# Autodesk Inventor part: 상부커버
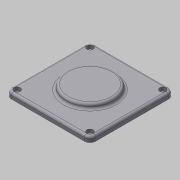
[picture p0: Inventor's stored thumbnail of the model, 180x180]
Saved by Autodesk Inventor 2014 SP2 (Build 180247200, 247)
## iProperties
Created: 2018-09
Part Number: 상부커버
Document SubType Name: Modeling
Density: 2.71 g/cm^3
Material: 알루미늄 6061
Mass: 249.405 g
Surface Area: 254.001 cm^2
Volume: 92.0315 cm^3
Appearance: 알루미늄 - 평지
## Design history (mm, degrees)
sketch "스케치5"
  geometry: L1 (-52.5, -52.5)-(52.5, -52.5); L2 (52.5, -52.5)-(52.5, 52.5); L3 (52.5, 52.5)-(-52.5, 52.5); L4 (-52.5, 52.5)-(-52.5, -52.5); L5 (-52.5, -52.5)-(52.5, 52.5); L6 (52.5, -52.5)-(-52.5, 52.5); 1 further point
  constraints: 12 end point, 2 midpoint, 2 parallel, 1 horizontal, 1 perpendicular
  dimensions: "d35" = 105 distance of L3.end L2.end; "d36" = 105 distance of L2.end L1.end
extrude "돌출4" new body sketch "스케치5" distance "d37" = 7; taper "d38" = 0 deg
fillet "모깎기4" dims "d39" = 7
sketch "스케치2"
  geometry: C1 r 30 at (0, 0); 2 further points
  constraints: 2 coincident, 1 centre point
  dimensions: "d4" = 60 diameter of C1
extrude "돌출3" join sketch "스케치2" distance "d5" = 6; taper "d6" = 0 deg
fillet "모깎기1" dims "d7" = 3
sketch "스케치4"
  geometry: L1 (52.5, -45.5)-(52.5, 45.5) reference; L2 (-45.5, -52.5)-(45.5, -52.5) reference; L3 (-52.5, 45.5)-(-52.5, -45.5) reference; L4 (45.5, 52.5)-(-45.5, 52.5) reference; A1 r 7 centre (45.5, 45.5) between (52.5, 45.5) and (45.5, 52.5) reference; A2 r 7 centre (45.5, -45.5) between (45.5, -52.5) and (52.5, -45.5) reference; A3 r 7 centre (-45.5, -45.5) between (-52.5, -45.5) and (-45.5, -52.5) reference; A4 r 7 centre (-45.5, 45.5) between (-45.5, 52.5) and (-52.5, 45.5) reference; 4 further points
  constraints: 4 coincident
hole "구멍3" sketch "스케치4" at (-45.5, 45.5), (-45.5, -45.5), (45.5, -45.5), (45.5, 45.5) diameter "d43" = 4.5; stored, may be unused: countersink angle "d47" = 90 deg, drill point angle "d49" = 118 deg; dims "d44" = 6, "d45" = 8, "d46" = 4.4, "d48" = 8
fillet "모깎기3" dims "d19" = 3
node "솔리드1"
node "솔리드2"
node "투영된 루프2"
